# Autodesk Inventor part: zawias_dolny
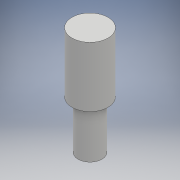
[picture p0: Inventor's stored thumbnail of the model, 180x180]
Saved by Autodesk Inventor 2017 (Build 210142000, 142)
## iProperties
Created: 2020-09
Part Number: zawias_dolny
Material: Generic
Document SubType Name: Modeling
Designer: WindowsX
Density: 1 g/cm^3
Appearance: Default
Author: WindowsX
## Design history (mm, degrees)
sketch "Szkic1"
  geometry: C1 r 15 at (0, 0); 1 further point
  constraints: 1 centre point, 1 coincident
  dimensions: "d1" = 30 diameter of C1
extrude "Wyciągnięcie proste1" new body sketch "Szkic1" distance "d2" = 50; taper "d3" = 0 deg
sketch "Szkic2"
  geometry: C1 r 10 at (0, 0); 1 further point
  constraints: 1 centre point, 1 coincident
  dimensions: "d4" = 20 diameter of C1
extrude "Wyciągnięcie proste2" join sketch "Szkic2" distance "d5" = 40; taper "d6" = 0 deg
node "Bryła1"
